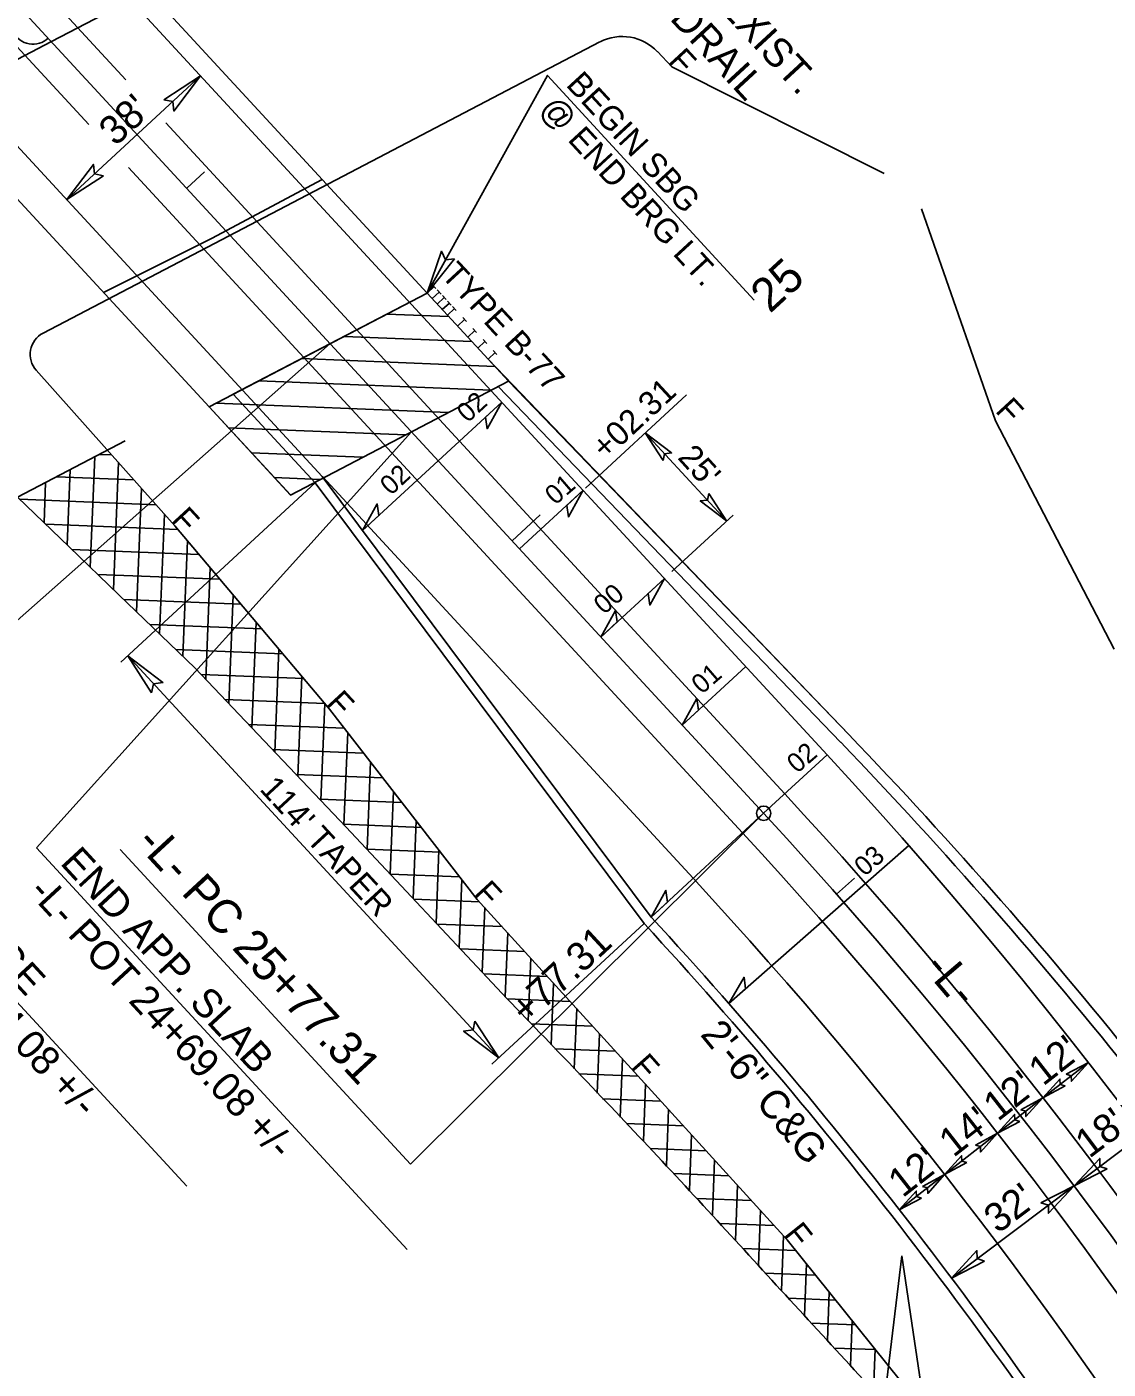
# Model space of a CAD drawing. Extents: x 1702862 to 1704514, y 793768 to 796215.
# Drawn here: x 1703570.3 to 1703795.7, y 794687 to 794966.9 of the extents above; entities that cross this region are included whole.
import ezdxf

# ---------------------------------------------------------------- set-up
doc = ezdxf.new("R2010")
doc.units = 0
for name, color, linetype in [('Prop Approach Slab', 7, 'Continuous'), ('Prop Conc 2ft 6in Curb and Gutter', 7, 'Continuous'), ('Prop Conc Shoulder Berm Gutter', 7, 'Continuous'), ('Prop Dimension', 7, 'Continuous'), ('Prop Dimension Text', 7, 'Continuous'), ('Prop DSN Text', 7, 'Continuous'), ('Prop EOT', 7, 'Continuous'), ('Prop Guardrail', 7, 'Continuous'), ('Prop Guardrail Anchor Unit CELL', 7, 'Continuous'), ('Prop Horizontal Alignment', 7, 'Continuous'), ('Prop Horizontal Alignment Direction Label', 7, 'Continuous'), ('Prop Horizontal Alignment Station Label', 7, 'Continuous'), ('Prop Horizontal Alignment Tick Label', 7, 'Continuous'), ('Prop Horizontal Alignment Tick Large', 7, 'Continuous'), ('Prop Horizontal Alignment Tick Small', 7, 'Continuous'), ('Prop Lane Lines', 7, 'Continuous'), ('Prop Leader Line Medium', 7, 'Continuous'), ('Prop Paved Shoulder', 7, 'Continuous'), ('Prop Rem of Exist Asph Pvmt', 7, 'Continuous'), ('Prop Roadway Bridge', 7, 'Continuous'), ('Prop SS Fill Line', 7, 'Continuous'), ('Prop SS Misc', 7, 'Continuous'), ('Prop Structure Anchor Unit CELL', 7, 'Continuous'), ('Prop Superelevation  Arrow CELL', 7, 'Continuous'), ('Prop Superelevation Label', 7, 'Continuous'), ('Prop Terminator CELL', 7, 'Continuous')]:
    doc.layers.add(name, color=color, linetype=linetype)

msp = doc.modelspace()

# ---------------------------------------------------------------- linework, layer by layer
at = {"layer": 'Prop Approach Slab'}
for p, q in [((1703653.75, 794911.37), (1703613.35, 794890.27)), ((1703653.75, 794911.37), (1703670.72, 794892.99)), ((1703645.37, 794906.99), (1703658.28, 794906.47)), ((1703636.47, 794902.34), (1703663.07, 794901.27)), ((1703627.57, 794897.69), (1703667.87, 794896.08)), ((1703618.66, 794893.04), (1703667.1, 794891.1)), ((1703670.72, 794892.99), (1703625.26, 794869.26)), ((1703609.76, 794888.39), (1703658.19, 794886.46)), ((1703608.29, 794887.64), (1703625.25, 794869.27)), ((1703612.31, 794883.29), (1703649.29, 794881.81)), ((1703617.1, 794878.09), (1703640.39, 794877.16)), ((1703621.9, 794872.9), (1703631.49, 794872.51))]:
    msp.add_line(p, q, dxfattribs=at)
msp.add_lwpolyline([(1703653.75, 794911.37), (1703670.72, 794892.99), (1703625.26, 794869.26), (1703608.3, 794887.63)], close=True, dxfattribs=at)
at = {"layer": 'Prop Conc 2ft 6in Curb and Gutter'}
for p, q in [((1703613.35, 794890.27), (1703630.43, 794871.77)), ((1703630.43, 794871.77), (1703699, 794779.93))]:
    msp.add_line(p, q, dxfattribs=at)
msp.add_arc((1702985.28, 794122.36), 970.46, 32.25438, 42.65517, dxfattribs=at)
at = {"layer": 'Prop Conc Shoulder Berm Gutter'}
msp.add_line((1703670.72, 794892.99), (1703741.68, 794819.32), dxfattribs=at)
msp.add_arc((1703001.88, 794109.24), 1025.44, 38.5857, 43.82566, dxfattribs=at)
at = {"layer": 'Prop Dimension'}
for p, q in [((1703578.62, 794930.85), (1703606.54, 794956.62)), ((1703589.93, 794834.39), (1703630.43, 794871.77)), ((1703591.37, 794835.71), (1703668.69, 794751.95)), ((1703667.25, 794750.62), (1703699, 794779.93)), ((1703791.62, 794750.99), (1703782.16, 794743.61)), ((1703782.16, 794743.61), (1703772.7, 794736.22)), ((1703772.7, 794736.22), (1703761.66, 794727.61)), ((1703803.04, 794736.07), (1703788.65, 794725.26)), ((1703761.66, 794727.61), (1703752.2, 794720.23)), ((1703788.65, 794725.26), (1703763.06, 794706.04)), ((1703752.73, 794710.66), (1703728.81, 794512.1)), ((1703752.73, 794710.66), (1703782.26, 794512.85))]:
    msp.add_line(p, q, dxfattribs=at)
msp.add_arc((1703571.59, 794967.94), 4.69, 207.6095, 312.7091, dxfattribs=at)
at = {"layer": 'Prop EOT'}
for p, q in [((1703259.9, 795332.15), (1703737.14, 794815.13)), ((1703418.98, 795103.79), (1703631.9, 794873.13)), ((1703631.9, 794873.13), (1703700.48, 794781.29))]:
    msp.add_line(p, q, dxfattribs=at)
msp.add_lwpolyline([(1703586.27, 794911.5), (1703608.79, 794922.72), (1703631.89, 794935.05)], dxfattribs=at)
for centre, radius, start, end in [((1702989.11, 794124.65), 1018, 14.75888, 42.70907), ((1702985.01, 794122.19), 972.78, 32.25419, 42.65174)]:
    msp.add_arc(centre, radius, start, end, dxfattribs=at)
at = {"layer": 'Prop Guardrail'}
for p, q in [((1703604.81, 794979.13), (1703575.44, 794963.77)), ((1703575.44, 794963.77), (1703500.62, 794924.67)), ((1703741.68, 794819.32), (1703666.47, 794897.59))]:
    msp.add_line(p, q, dxfattribs=at)
msp.add_arc((1703001.88, 794109.24), 1025.44, 38.5857, 43.82566, dxfattribs=at)
at = {"layer": 'Prop Horizontal Alignment'}
msp.add_line((1703246.67, 795319.94), (1703723.92, 794802.92), dxfattribs=at)
msp.add_arc((1702989.11, 794124.65), 1000, 351.25916, 42.70907, dxfattribs=at)
at = {"layer": 'Prop Horizontal Alignment Station Label'}
for p in [(1703723.92, 794802.92), (1703589.75, 794795.36)]:
    msp.add_line(p, (1703650.3, 794729.77), dxfattribs=at)
msp.add_circle((1703723.92, 794802.92), 1.5, dxfattribs=at)
at = {"layer": 'Prop Horizontal Alignment Tick Large'}
msp.add_line((1703671.48, 794859.73), (1703677.36, 794865.16), dxfattribs=at)
at = {"layer": 'Prop Horizontal Alignment Tick Small'}
for p, q in [((1703603.65, 794933.21), (1703607.32, 794936.6)), ((1703739.12, 794786.08), (1703742.87, 794789.38))]:
    msp.add_line(p, q, dxfattribs=at)
at = {"layer": 'Prop Lane Lines'}
for p, q in [((1703558.4, 794991.09), (1703590.98, 794955.79)), ((1703549.28, 794983.27), (1703583.2, 794946.52)), ((1703599.26, 794946.81), (1703728.33, 794806.99)), ((1703591.49, 794937.54), (1703719.51, 794798.85)), ((1703631.99, 794873.03), (1703710.03, 794788.48))]:
    msp.add_line(p, q, dxfattribs=at)
for radius, start in [(1006, 0.00687), (994, 359.40932), (980, 359.40932)]:
    msp.add_arc((1702989.11, 794124.65), radius, start, 42.70907, dxfattribs=at)
at = {"layer": 'Prop Leader Line Medium'}
for p, q in [((1703633.55, 794900.82), (1703527.8, 794807.39)), ((1703650.51, 794882.45), (1703572.33, 794795.7)), ((1703527.8, 794807.39), (1703603.65, 794725.22)), ((1703572.33, 794795.7), (1703649.6, 794711.99))]:
    msp.add_line(p, q, dxfattribs=at)
msp.add_lwpolyline([(1703653.75, 794911.37), (1703678.87, 794956.74), (1703721.97, 794909.87)], dxfattribs=at)
at = {"layer": 'Prop Paved Shoulder'}
msp.add_line((1703668.56, 794891.87), (1703740, 794817.7), dxfattribs=at)
msp.add_arc((1703001.88, 794109.24), 1023.11, 38.5857, 43.82566, dxfattribs=at)
at = {"layer": 'Prop Rem of Exist Asph Pvmt'}
for p, q in [((1703584.45, 794877.22), (1703583.53, 794854.21)), ((1703585.42, 794877.73), (1703587.97, 794877.62)), ((1703579.34, 794874.54), (1703578.71, 794858.85)), ((1703589.41, 794876.02), (1703588.35, 794849.57)), ((1703574.23, 794871.86), (1703573.9, 794863.49)), ((1703576.55, 794873.08), (1703592.6, 794872.44)), ((1703594.2, 794870.64), (1703593.17, 794844.93)), ((1703568.82, 794868.38), (1703597.22, 794867.25)), ((1703574.24, 794863.16), (1703601.81, 794862.06)), ((1703598.99, 794865.27), (1703597.99, 794840.29)), ((1703579.66, 794857.94), (1703606.18, 794856.88)), ((1703603.77, 794859.74), (1703602.81, 794835.65)), ((1703585.08, 794852.72), (1703610.56, 794851.7)), ((1703608.55, 794854.08), (1703607.62, 794830.82)), ((1703590.5, 794847.5), (1703614.93, 794846.52)), ((1703613.32, 794848.42), (1703612.42, 794825.77)), ((1703595.93, 794842.28), (1703619.3, 794841.34)), ((1703618.1, 794842.77), (1703617.22, 794820.71)), ((1703601.35, 794837.06), (1703623.68, 794836.16)), ((1703622.88, 794837.11), (1703622.02, 794815.66)), ((1703606.65, 794831.84), (1703628.05, 794830.99)), ((1703627.66, 794831.45), (1703626.82, 794810.61)), ((1703611.59, 794826.64), (1703632.42, 794825.81)), ((1703632.44, 794825.79), (1703631.63, 794805.55)), ((1703616.53, 794821.44), (1703636.52, 794820.64)), ((1703637.2, 794819.76), (1703636.43, 794800.5)), ((1703621.47, 794816.24), (1703640.53, 794815.47)), ((1703641.96, 794813.63), (1703641.23, 794795.39)), ((1703626.42, 794811.03), (1703644.54, 794810.31)), ((1703646.72, 794807.5), (1703646.03, 794790.27)), ((1703631.36, 794805.83), (1703648.55, 794805.15)), ((1703651.47, 794801.37), (1703650.83, 794785.15)), ((1703636.3, 794800.63), (1703652.56, 794799.98)), ((1703641.18, 794795.43), (1703656.57, 794794.82)), ((1703656.23, 794795.24), (1703655.62, 794780.04)), ((1703646.06, 794790.23), (1703660.57, 794789.65)), ((1703660.99, 794789.12), (1703660.42, 794774.92)), ((1703650.94, 794785.03), (1703664.65, 794784.49)), ((1703665.76, 794783.27), (1703665.22, 794769.81)), ((1703655.82, 794779.83), (1703669.39, 794779.29)), ((1703670.56, 794778.01), (1703670.02, 794764.7)), ((1703660.69, 794774.64), (1703674.12, 794774.1)), ((1703675.35, 794772.75), (1703674.83, 794759.67)), ((1703665.57, 794769.44), (1703678.85, 794768.91)), ((1703680.14, 794767.49), (1703679.63, 794754.65)), ((1703670.47, 794764.24), (1703683.59, 794763.71)), ((1703684.94, 794762.23), (1703684.43, 794749.62)), ((1703675.44, 794759.03), (1703688.32, 794758.52)), ((1703689.73, 794756.97), (1703689.23, 794744.59)), ((1703680.41, 794753.83), (1703693.05, 794753.32)), ((1703694.52, 794751.71), (1703694.04, 794739.57)), ((1703685.38, 794748.63), (1703697.79, 794748.13)), ((1703699.32, 794746.45), (1703698.84, 794734.54)), ((1703690.35, 794743.42), (1703702.51, 794742.94)), ((1703704.11, 794741.18), (1703703.64, 794729.5)), ((1703695.32, 794738.22), (1703707.23, 794737.75)), ((1703708.9, 794735.91), (1703708.44, 794724.38)), ((1703700.29, 794733.02), (1703711.96, 794732.55)), ((1703713.7, 794730.64), (1703713.24, 794719.19)), ((1703705.23, 794727.82), (1703716.68, 794727.36)), ((1703718.49, 794725.37), (1703718.03, 794713.96)), ((1703710.07, 794722.62), (1703721.41, 794722.17)), ((1703714.86, 794717.42), (1703726.13, 794716.97)), ((1703723.28, 794720.1), (1703722.83, 794708.7)), ((1703728.08, 794714.84), (1703727.62, 794703.44)), ((1703719.61, 794712.23), (1703730.61, 794711.79)), ((1703732.85, 794709.01), (1703732.41, 794698.21)), ((1703724.34, 794707.04), (1703734.77, 794706.62)), ((1703729.08, 794701.84), (1703738.93, 794701.45)), ((1703737.61, 794703.09), (1703737.21, 794693.01)), ((1703733.85, 794696.65), (1703743.09, 794696.28)), ((1703742.38, 794697.16), (1703742.01, 794687.84)), ((1703738.66, 794691.45), (1703747.25, 794691.11)), ((1703747.15, 794691.23), (1703746.8, 794682.65))]:
    msp.add_line(p, q, dxfattribs=at)
for points in [[(1703568.38, 794868.8), (1703590.81, 794880.55)], [(1703579.1, 794858.48), (1703568.38, 794868.8)], [(1703579.1, 794858.48), (1703589.48, 794848.49)], [(1703669.4, 794765.36), (1703636.82, 794800.09), (1703605.39, 794833.16), (1703589.48, 794848.49)]]:
    msp.add_lwpolyline(points, dxfattribs=at)
msp.add_spline([(1703779.68, 794644.96), (1703761.75, 794665.91), (1703731.32, 794699.4), (1703700.82, 794732.47), (1703669.4, 794765.36)], degree=3, dxfattribs=at)
at = {"layer": 'Prop Roadway Bridge'}
for p, q in [((1703531.64, 795043.66), (1703653.75, 794911.37)), ((1703486.23, 795019.87), (1703608.29, 794887.64)), ((1703608.29, 794887.64), (1703653.75, 794911.37))]:
    msp.add_line(p, q, dxfattribs=at)
at = {"layer": 'Prop SS Fill Line'}
for p, q in [((1703689.78, 794963.74), (1703573.68, 794903.01)), ((1703704.77, 794958.5), (1703701.8, 794961.69)), ((1703704.77, 794958.5), (1703749.05, 794936.28)), ((1703756.85, 794928.93), (1703772.29, 794884.75)), ((1703572.26, 794895.26), (1703601.14, 794862.85)), ((1703772.29, 794884.75), (1703797.01, 794837.14)), ((1703601.14, 794862.85), (1703633.43, 794824.61)), ((1703633.43, 794824.61), (1703664.21, 794784.97)), ((1703664.21, 794784.97), (1703697.03, 794748.96)), ((1703697.03, 794748.96), (1703728.84, 794713.99)), ((1703728.84, 794713.99), (1703758.51, 794677.1))]:
    msp.add_line(p, q, dxfattribs=at)
for centre, radius, start, end in [((1703694.44, 794954.84), 10, 42.932, 117.6095), ((1703576, 794898.58), 5, 117.6095, 221.704)]:
    msp.add_arc(centre, radius, start, end, dxfattribs=at)
at = {"layer": 'Prop Structure Anchor Unit CELL'}
for p, q in [((1703653.75, 794911.37), (1703655.22, 794912.73)), ((1703653.75, 794911.37), (1703666.47, 794897.59)), ((1703654.81, 794910.22), (1703656.28, 794911.58)), ((1703654.83, 794913.15), (1703655.61, 794912.31)), ((1703655.89, 794912), (1703656.67, 794911.16)), ((1703656.95, 794910.85), (1703657.73, 794910.01)), ((1703655.87, 794909.07), (1703657.34, 794910.43)), ((1703656.93, 794907.93), (1703658.4, 794909.28)), ((1703657.99, 794906.78), (1703659.46, 794908.13)), ((1703658.01, 794909.7), (1703658.79, 794908.86)), ((1703659.07, 794908.55), (1703659.85, 794907.71)), ((1703660.11, 794904.48), (1703661.58, 794905.84)), ((1703661.19, 794906.26), (1703661.97, 794905.42)), ((1703662.23, 794902.18), (1703663.7, 794903.54)), ((1703663.31, 794903.96), (1703664.09, 794903.12)), ((1703664.35, 794899.89), (1703665.82, 794901.24)), ((1703665.43, 794901.67), (1703666.21, 794900.82)), ((1703667.55, 794899.37), (1703668.33, 794898.53)), ((1703666.47, 794897.59), (1703667.94, 794898.95))]:
    msp.add_line(p, q, dxfattribs=at)
at = {"layer": 'Prop Superelevation  Arrow CELL'}
for p, q in [((1703656.09, 794876.4), (1703669.31, 794888.61)), ((1703640.32, 794861.85), (1703656.09, 794876.4)), ((1703673.05, 794858.03), (1703686.27, 794870.24)), ((1703690, 794839.66), (1703703.23, 794851.87)), ((1703706.96, 794821.29), (1703720.19, 794833.5)), ((1703723.92, 794802.92), (1703737.14, 794815.13)), ((1703723.92, 794802.92), (1703700.48, 794781.29)), ((1703740.64, 794784.34), (1703754.17, 794796.22)), ((1703740.64, 794784.34), (1703716.65, 794763.28))]:
    msp.add_line(p, q, dxfattribs=at)
for points in [[(1703669.31, 794888.61), (1703666.26, 794883.07), (1703665.92, 794885.48)], [(1703686.27, 794870.24), (1703683.22, 794864.7), (1703682.87, 794867.11)], [(1703640.32, 794861.85), (1703643.37, 794867.39), (1703643.72, 794864.98)], [(1703703.23, 794851.87), (1703700.18, 794846.33), (1703699.83, 794848.74)], [(1703690, 794839.66), (1703693.05, 794845.2), (1703693.4, 794842.8)], [(1703706.96, 794821.29), (1703710.01, 794826.83), (1703710.36, 794824.43)], [(1703700.48, 794781.29), (1703703.53, 794786.83), (1703703.87, 794784.42)], [(1703716.65, 794763.28), (1703719.84, 794768.75), (1703720.13, 794766.34)]]:
    msp.add_lwpolyline(points, close=True, dxfattribs=at)
at = {"layer": 'Prop Superelevation Label'}
for p, q in [((1703686.79, 794870.72), (1703707.87, 794890.18)), ((1703699.24, 794882.21), (1703716.21, 794863.85)), ((1703704.77, 794853.3), (1703717.55, 794865.09))]:
    msp.add_line(p, q, dxfattribs=at)
for points in [[(1703702.97, 794876.47), (1703699.24, 794882.21), (1703704.73, 794878.04), (1703703.26, 794877.86)], [(1703712.48, 794869.6), (1703716.21, 794863.85), (1703710.72, 794868.02), (1703712.19, 794868.2)]]:
    msp.add_lwpolyline(points, close=True, dxfattribs=at)
at = {"layer": 'Prop Terminator CELL'}
for points in [[(1703598.87, 794951.66), (1703606.54, 794956.62), (1703600.97, 794949.31), (1703600.73, 794951.26)], [(1703586.28, 794935.81), (1703578.62, 794930.85), (1703584.18, 794938.16), (1703584.42, 794936.21)], [(1703659.47, 794918.49), (1703653.75, 794911.37), (1703656.74, 794920.06), (1703657.58, 794918.28)], [(1703596.33, 794828.05), (1703591.37, 794835.71), (1703598.68, 794830.15), (1703596.72, 794829.91)], [(1703663.72, 794759.61), (1703668.69, 794751.95), (1703661.38, 794757.51), (1703663.33, 794757.75)], [(1703786.99, 794748.51), (1703791.62, 794750.99), (1703788.08, 794747.06), (1703788.04, 794748.19)], [(1703786.79, 794746.09), (1703782.16, 794743.61), (1703785.69, 794747.53), (1703785.74, 794746.4)], [(1703777.53, 794741.12), (1703782.16, 794743.61), (1703778.62, 794739.68), (1703778.58, 794740.81)], [(1703777.33, 794738.7), (1703772.7, 794736.22), (1703776.23, 794740.15), (1703776.28, 794739.02)], [(1703768.07, 794733.74), (1703772.7, 794736.22), (1703769.16, 794732.3), (1703769.12, 794733.43)], [(1703766.29, 794730.09), (1703761.66, 794727.61), (1703765.2, 794731.54), (1703765.24, 794730.4)], [(1703795.55, 794728.81), (1703788.65, 794725.26), (1703793.98, 794730.97), (1703794.02, 794729.3)], [(1703757.03, 794725.13), (1703761.66, 794727.61), (1703758.13, 794723.68), (1703758.08, 794724.81)], [(1703756.83, 794722.71), (1703752.2, 794720.23), (1703755.74, 794724.15), (1703755.78, 794723.02)], [(1703781.74, 794721.72), (1703788.65, 794725.26), (1703783.31, 794719.56), (1703783.28, 794721.23)], [(1703769.97, 794709.59), (1703763.06, 794706.04), (1703768.39, 794711.75), (1703768.43, 794710.08)]]:
    msp.add_lwpolyline(points, close=True, dxfattribs=at)

# ---------------------------------------------------------------- texts
at = {"layer": 'Prop Dimension Text'}
for s, height, rotation, p in [('TIE TO EXIST.', 6, 312.7091, (1703695.07, 794991.61)), ('GUARDRAIL', 6, 312.7091, (1703688.46, 794985.51)), ("38'", 6, 42.7091, (1703588.79, 794941.8)), ("114' TAPER", 5, 312.7091, (1703618.65, 794807.83)), ('+77.31', 6, 42.7091, (1703674.52, 794758.7)), ('2\'-6" C&G', 6, 309.2167, (1703710.55, 794756.76)), ("12'", 6, 37.9714, (1703782.19, 794745.92)), ("12'", 6, 37.9714, (1703772.75, 794738.55)), ("14'", 6, 37.9714, (1703763.5, 794731.04)), ("18'", 6, 36.9141, (1703791.81, 794730.85)), ("12'", 6, 37.9714, (1703752.9, 794722.64)), ("32'", 6, 36.9141, (1703772.77, 794715.15))]:
    msp.add_text(s, height=height, rotation=rotation, dxfattribs=at).set_placement(p)
at = {"layer": 'Prop DSN Text'}
for s, height, p in [('BEGIN SBG', 5, (1703682.53, 794954.65)), ('@ END BRG LT.', 5, (1703677.02, 794949.57)), ('END BRIDGE', 6, (1703536.36, 794801.21)), ('-L- POT 24+44.08 +/-', 6, (1703529.75, 794795.11)), ('END APP. SLAB', 6, (1703577.06, 794792.44)), ('-L- POT 24+69.08 +/-', 6, (1703570.45, 794786.33))]:
    msp.add_text(s, height=height, rotation=312.7091, dxfattribs=at).set_placement(p)
at = {"layer": 'Prop Guardrail Anchor Unit CELL'}
msp.add_text('TYPE B-77', height=5, rotation=312.7301, dxfattribs=at).set_placement((1703656.47, 794914.94))
at = {"layer": 'Prop Horizontal Alignment Direction Label'}
msp.add_text('-L-', height=7, rotation=310.3963, dxfattribs=at).set_placement((1703757, 794770.57))
at = {"layer": 'Prop Horizontal Alignment Station Label'}
msp.add_text('-L- PC 25+77.31', height=7, rotation=312.7091, dxfattribs=at).set_placement((1703592.8, 794796.58))
at = {"layer": 'Prop Horizontal Alignment Tick Label'}
msp.add_text('25', height=7, rotation=42.7091, dxfattribs=at).set_placement((1703725.24, 794906.98))
at = {"layer": 'Prop SS Misc'}
for rotation, p in [(312.7091, (1703703.8, 794959.54)), (312.7091, (1703772.03, 794886.69)), (312.7091, (1703600.18, 794863.89)), (312.7091, (1703632.47, 794825.65)), (312.7091, (1703663.25, 794786.02)), (311.4091, (1703696.09, 794750.03)), (308.5443, (1703727.96, 794715.1))]:
    msp.add_text('F', height=5, rotation=rotation, dxfattribs=at).set_placement(p)
at = {"layer": 'Prop Superelevation Label'}
for s, height, rotation, p in [('+02.31', 5, 42.7097, (1703690.92, 794876.4)), ('02', 4, 42.7091, (1703662.23, 794884.17)), ("25'", 5, 312.1969, (1703705.81, 794876.95)), ('02', 4, 42.7091, (1703646.21, 794869.03)), ('01', 4, 40.7995, (1703680.48, 794867.02)), ('00', 4, 40.7995, (1703690.64, 794844.2)), ('01', 4, 40.7995, (1703711.01, 794827.59)), ('02', 4, 40.7995, (1703730.91, 794811.09)), ('03', 4, 41.2768, (1703744.98, 794789.6))]:
    msp.add_text(s, height=height, rotation=rotation, dxfattribs=at).set_placement(p)

doc.saveas('drawing.dxf')
